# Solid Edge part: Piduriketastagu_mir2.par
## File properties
Author: Türk
Template: Iso Part.par
Last saved by: Türk
Revision: 3
Application: Solid Edge
Accuracy: 0,990
Username: Türk
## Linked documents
Piduriketastagu_mir.par
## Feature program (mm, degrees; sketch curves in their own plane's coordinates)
part copy "CopiedPart_1"
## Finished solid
Body 1: solid body, 367 faces, 930 edges, 578 vertices.
  Faces by surface: plane 206, swept 68, cone 35, spline 34, cylinder 24
  Edges by curve: line 374, circle 250, spline 170, intersection 102, curve on surface 34
Bounding box of the edges (mm; curved faces can reach further): 260.000 x 30.000 x 260.000, from (-130, -15, -130) to (130, 15, 130).
Cylindrical faces by radius (mm): R6 x5, R62.1667 x17, R62.5 x1, R130 x1
Conical faces (half-angle, radius in mm at the cone's reference point): 18.4349 deg R57.5 x1, 45 deg R129 x17, 45 deg R130 x17
Planar faces by outward normal: +y 52, -y 69, oblique 85
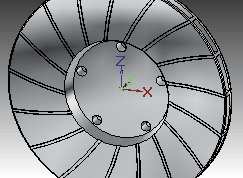
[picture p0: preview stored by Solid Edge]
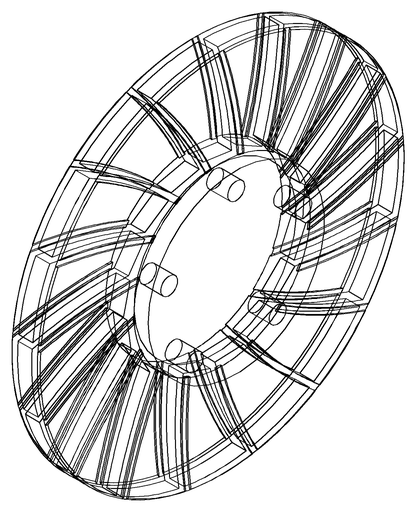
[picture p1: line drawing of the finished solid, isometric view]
